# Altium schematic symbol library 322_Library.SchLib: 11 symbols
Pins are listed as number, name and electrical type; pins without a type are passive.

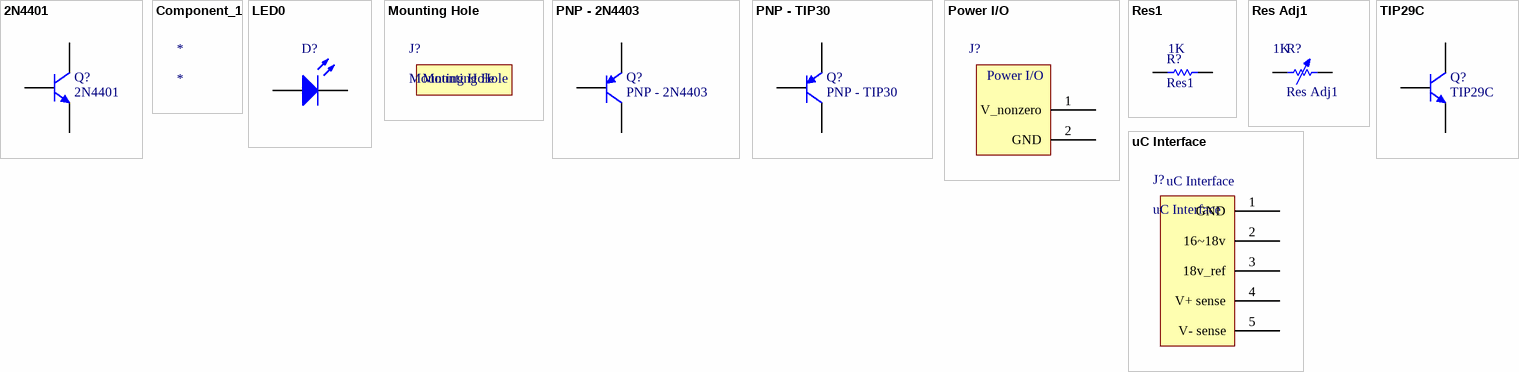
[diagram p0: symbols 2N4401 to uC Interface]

## 2N4401
designator Q?
NPN General Purpose Amplifier
footprint TO-92A - BJT (TO, Flat Index; 3 In-Line, Axial Leads; Body Dia. 4.5mm; Leads 0.51 x 0.48 mm (max))
pins: 1 C, 2 B, 3 E

## Component_1
designator *

## LED0
designator D?
Typical INFRARED GaAs LED
footprint Basic_LED - Through hole
pins: 1 A, 2 K

## Mounting Hole
designator J?
footprint Mounting Hole

## PNP - 2N4403
designator Q?
PNP Bipolar Transistor
simulation model PNP
signal-integrity model PNP
footprint TO-92A - BJT (TO, Flat Index; 3 In-Line, Axial Leads; Body Dia. 4.5mm; Leads 0.51 x 0.48 mm (max))
pins: 1 C, 2 B, 3 E

## PNP - TIP30
designator Q?
PNP Bipolar Transistor
simulation model PNP
signal-integrity model PNP
footprint TO-220AB (TO, Thru-Hole, Vertical, Heatsink Mounted; 3 In-Line Leads; Pitch 2.54 mm)
pins: 1 B, 2 C, 3 E

## Power I/O
designator J?  (value not drawn)
footprint POWER CONNECTIONS
pins: 1 V_nonzero, 2 GND

## Res1
designator R?  value 1K
Resistor
footprint AXIAL-0.3 (Axial Device, Thru-Hole; 2 Leads; 0.3 in Pin Spacing)
pins: 1, 2

## Res Adj1
designator R?  value 1K
Variable Resistor
simulation model VRES (Variable Resistor)
signal-integrity model Res Adj
footprint POT Connections (Connection for an external potentiometer)
pins: 1, 2

## TIP29C
designator Q?
NPN General Purpose Amplifier
simulation model 2N3904 (NPN)
signal-integrity model 2N3904
footprint TO-220AB (TO, Thru-Hole, Vertical, Heatsink Mounted; 3 In-Line Leads; Pitch 2.54 mm)
pins: 1 B, 2 C, 3 E

## uC Interface
designator J?
footprint uC Interface
pins: 1 GND, 2 16~18v, 3 18v_ref, 4 V+ sense, 5 V- sense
